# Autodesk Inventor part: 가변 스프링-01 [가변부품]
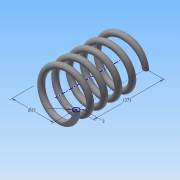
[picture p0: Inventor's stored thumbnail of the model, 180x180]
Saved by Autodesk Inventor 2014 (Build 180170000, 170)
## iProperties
Created: 2015-09
Part Number: 가변 스프링-01 [가변부품]
Material: 강철, 탄소
Document SubType Name: Modeling
Designer: study
Density: 7.87 g/cm^3
Appearance: 반연마
Mass: 18.8456 g
Surface Area: 32.507 cm^2
Volume: 2.39462 cm^3
Author: study
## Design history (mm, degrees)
sketch "스케치1"
  geometry: L1 (0, 0)-(11, 0); L2 (11, 0)-(11, 40.095); L3 (11, 40.095)-(0, 40.095); L4 (0, 40.095)-(0, 0); C1 r 1.5 at (11, 0)
  constraints: 8 end point, 2 parallel, 1 centre point, 1 coincident, 1 horizontal, 1 perpendicular
  dimensions: "d0" = 3 diameter of C1; "d1" = 40.0955 distance between parallel lines of L3 L1 (derived); "d2" = 22 diameter of L2 L4
feature "코일1" sketch "스케치1" pitch "d3" = 10; turns "d5" = 5; dims "d4" = 40.0955 (= d1), "d6" = 0, angle "d7" = 90 deg, angle "d8" = 90 deg, "d9" = 0, "d10" = 0
node "작업 평면1"
sketch "스케치2"
  geometry: L1 (-12.5, 0)-(-9.5, 0) reference; 1 further point
  constraints: 1 horizontal alignment
extrude "돌출1" cut sketch "스케치2" stored distance "d12" = 10; taper "d13" = 0 deg
node "작업 평면2"
sketch "스케치3"
  geometry: L1 (-9.5, 0)-(-12.5, 0) reference; 1 further point
  constraints: 1 horizontal alignment
extrude "돌출2" cut sketch "스케치3" stored distance "d15" = 10; taper "d16" = 0 deg
node "솔리드1"
node "절단 모서리 투영1"
node "절단 모서리 투영2"
other parameters: "d11" = 0, "d14" = 40.0955 (= d1)
